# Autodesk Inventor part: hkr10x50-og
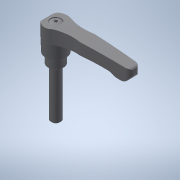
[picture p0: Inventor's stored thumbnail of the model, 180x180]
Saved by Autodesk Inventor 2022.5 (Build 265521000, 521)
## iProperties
Created: 2017-09
Part Number: hkr10x50-og
Material: 一般
Document SubType Name: Modeling
Designer: imaocorp
Density: 1 g/cm^3
Appearance: 既定
Author: imaocorp
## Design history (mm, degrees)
node "hkr10x50-og.x_t1"
node "hkr10x50-og"
node "Base1"
